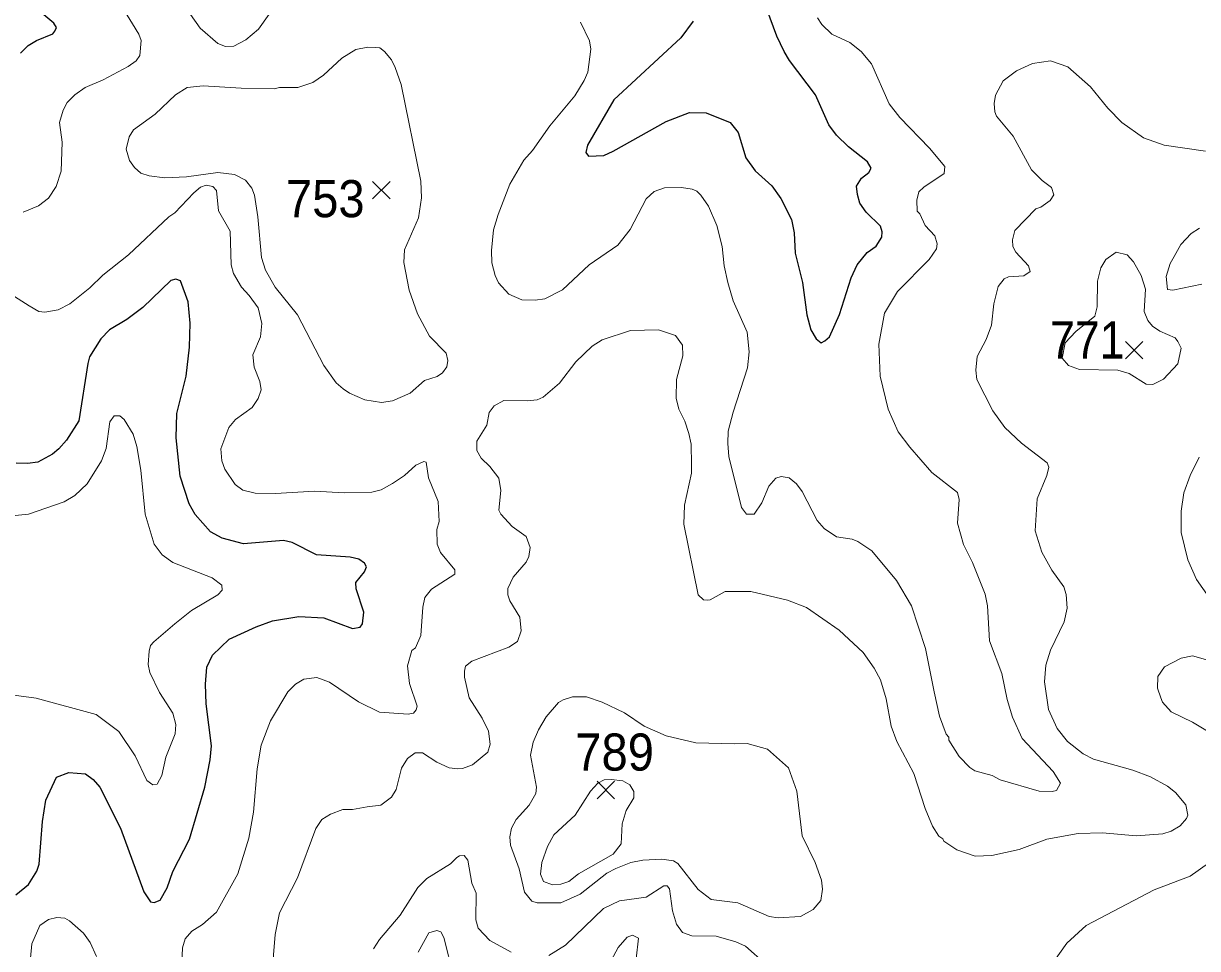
# Model space of a CAD drawing. Extents: x 294.2 to 320.3, y 7482.7 to 7510.7.
# Drawn here: x 305.089 to 307.621, y 7505.286 to 7507.28 of the extents above; entities that cross this region are included whole.
import ezdxf
from ezdxf.enums import TextEntityAlignment as Align

# ---------------------------------------------------------------- set-up
doc = ezdxf.new("R2010")
doc.units = 0
doc.header["$LTSCALE"] = 0.032
for name, color, linetype, lineweight in [('1', 7, 'Continuous', 25), ('2', 7, 'Continuous', 13), ('21', 7, 'Continuous', 25)]:
    doc.layers.add(name, color=color, linetype=linetype, lineweight=lineweight)
doc.layers.add('61', color=7, linetype='Continuous')

msp = doc.modelspace()

# ---------------------------------------------------------------- linework, layer by layer
at = {"layer": '1'}
for points in [[(305.0821, 7507.2166), (305.0986, 7507.2331), (305.1167, 7507.2441), (305.1517, 7507.2583), (305.1564, 7507.2638), (305.1596, 7507.2716), (305.154, 7507.2811), (305.1116, 7507.3164), (305.099, 7507.3337), (305.0861, 7507.3695)], [(306.5328, 7507.2852), (306.5061, 7507.2494), (306.3616, 7507.1158), (306.3048, 7507.0182), (306.3016, 7507.0025), (306.3071, 7506.9947), (306.3401, 7506.9962), (306.3606, 7507.0049), (306.4747, 7507.0695), (306.5254, 7507.0884), (306.5608, 7507.0876), (306.6127, 7507.0672), (306.63, 7507.0452), (306.6469, 7506.9909), (306.6666, 7506.9626), (306.7027, 7506.9304), (306.7224, 7506.9029), (306.7448, 7506.8581), (306.7511, 7506.829), (306.7527, 7506.785), (306.7687, 7506.722), (306.7782, 7506.652), (306.7868, 7506.6198), (306.7982, 7506.6009), (306.8092, 7506.5923), (306.8171, 7506.5962), (306.8273, 7506.6049), (306.8485, 7506.6528), (306.8737, 7506.7322), (306.887, 7506.7605), (306.9086, 7506.7864), (306.9275, 7506.8006), (306.9401, 7506.8195), (306.9409, 7506.8313), (306.9369, 7506.8438), (306.9058, 7506.874), (306.8922, 7506.8929), (306.8875, 7506.9117), (306.8851, 7506.9298), (306.8961, 7506.9471), (306.9118, 7506.9589), (306.9166, 7506.9684), (306.9087, 7506.9825), (306.8678, 7507.0147), (306.8419, 7507.0394), (306.8259, 7507.0622), (306.7966, 7507.1267), (306.7407, 7507.2006), (306.7295, 7507.2201), (306.7136, 7507.2533), (306.6921, 7507.3115)], [(305.072, 7505.4017), (305.0995, 7505.424), (305.1174, 7505.4528), (305.1225, 7505.4681), (305.1295, 7505.56), (305.1371, 7505.606), (305.1601, 7505.6558), (305.1863, 7505.666), (305.2221, 7505.6628), (305.2393, 7505.6507), (305.2534, 7505.6341), (305.298, 7505.5459), (305.3479, 7505.4081), (305.3625, 7505.387), (305.3702, 7505.3851), (305.3836, 7505.3902), (305.3989, 7505.417), (305.4111, 7505.4521), (305.4468, 7505.5217), (305.48, 7505.6341), (305.4915, 7505.6928), (305.4941, 7505.7235), (305.4826, 7505.8135), (305.4813, 7505.8563), (305.4839, 7505.8926), (305.4962, 7505.9185), (305.5324, 7505.9531), (305.5904, 7505.9799), (305.6258, 7505.9924), (305.6824, 7506.0019), (305.7362, 7505.9988), (305.7983, 7505.976), (305.8151, 7505.9787), (305.8201, 7505.9863), (305.8224, 7506.0115), (305.8064, 7506.0618), (305.8056, 7506.0752), (305.8245, 7506.098), (305.8282, 7506.109), (305.8243, 7506.1169), (305.8117, 7506.1255), (305.7936, 7506.1302), (305.7205, 7506.135), (305.6682, 7506.1617), (305.6493, 7506.1656), (305.5633, 7506.1585), (305.5169, 7506.1711), (305.4917, 7506.1845), (305.4587, 7506.2222), (305.4457, 7506.245), (305.4269, 7506.3048), (305.4178, 7506.3873), (305.4194, 7506.44), (305.4395, 7506.5201), (305.4466, 7506.583), (305.4481, 7506.6342), (305.4438, 7506.6806), (305.4273, 7506.7254), (305.417, 7506.7293), (305.4068, 7506.7262), (305.3463, 7506.668), (305.3114, 7506.6421), (305.2745, 7506.6201), (305.2556, 7506.6004), (305.2312, 7506.5619), (305.2273, 7506.5477), (305.208, 7506.4235), (305.1813, 7506.3819), (305.1652, 7506.3638), (305.151, 7506.352), (305.1196, 7506.3347), (305.0976, 7506.3316), (305.0732, 7506.3324)]]:
    msp.add_lwpolyline(points, dxfattribs=at)
at = {"layer": '2'}
for points in [[(305.088, 7506.874), (305.1212, 7506.8874), (305.1429, 7506.904), (305.1589, 7506.9289), (305.1697, 7506.9621), (305.1722, 7507.0247), (305.1665, 7507.0668), (305.1742, 7507.0936), (305.1831, 7507.1102), (305.1997, 7507.1268), (305.2214, 7507.1421), (305.2604, 7507.1587), (305.3146, 7507.1875), (305.3319, 7507.2003), (305.3395, 7507.2111), (305.3428, 7507.2437), (305.3377, 7507.2571), (305.2853, 7507.3439)], [(305.4034, 7507.3644), (305.4698, 7507.2705), (305.5081, 7507.2373), (305.5247, 7507.2309), (305.5426, 7507.2315), (305.5681, 7507.2449), (305.5956, 7507.2679), (305.6186, 7507.3005)], [(307.3163, 7505.6271), (307.3252, 7505.6424), (307.3093, 7505.6679), (307.2429, 7505.7388), (307.2218, 7505.7848), (307.2103, 7505.8231), (307.1988, 7505.8793), (307.172, 7505.9495), (307.1681, 7506.0248), (307.163, 7506.0504), (307.1356, 7506.1181), (307.1164, 7506.157), (307.103, 7506.2029), (307.1064, 7506.2539), (307.103, 7506.2695), (307.0481, 7506.3128), (307.0002, 7506.367), (306.9753, 7506.4002), (306.9536, 7506.4488), (306.9364, 7506.5203), (306.9332, 7506.5893), (306.9459, 7506.6556), (306.974, 7506.7029), (307.0417, 7506.7718), (307.0577, 7506.7948), (307.059, 7506.8051), (307.0545, 7506.8229), (307.0334, 7506.8452), (307.0219, 7506.8701), (307.0162, 7506.8759), (307.0156, 7506.8995), (307.0194, 7506.9174), (307.0302, 7506.9276), (307.0744, 7506.9568), (307.0756, 7506.9718), (307.0428, 7507.0114), (306.9786, 7507.0779), (306.9556, 7507.1074), (306.9177, 7507.1935), (306.8955, 7507.22), (306.8706, 7507.2392), (306.8323, 7507.2571), (306.8106, 7507.2781), (306.801, 7507.2929)], [(306.2903, 7507.2832), (306.3094, 7507.2431), (306.3126, 7507.2252), (306.3056, 7507.1754), (306.2979, 7507.1575), (306.2775, 7507.1243), (306.2238, 7507.0598), (306.1868, 7507.0068), (306.1677, 7506.9857), (306.1376, 7506.934), (306.1121, 7506.8689), (306.1025, 7506.8357), (306.098, 7506.791), (306.0987, 7506.7642), (306.1057, 7506.7374), (306.1134, 7506.7214), (306.1357, 7506.6971), (306.1632, 7506.685), (306.1926, 7506.6837), (306.213, 7506.6869), (306.2513, 7506.7061), (306.3088, 7506.7603), (306.3707, 7506.8025), (306.3975, 7506.8363), (306.432, 7506.9027), (306.4492, 7506.9181), (306.4709, 7506.9263), (306.508, 7506.927), (306.531, 7506.9232), (306.5412, 7506.9187), (306.5495, 7506.9104), (306.5661, 7506.8868), (306.584, 7506.8446), (306.5954, 7506.7999), (306.5999, 7506.7578), (306.6075, 7506.7221), (306.619, 7506.6825), (306.6497, 7506.6148), (306.6535, 7506.5726), (306.6504, 7506.5382), (306.619, 7506.4424), (306.6088, 7506.4015), (306.6075, 7506.3747), (306.6101, 7506.3473), (306.6376, 7506.2368), (306.6478, 7506.2227), (306.6644, 7506.2227), (306.681, 7506.247), (306.6963, 7506.2828), (306.711, 7506.3), (306.7225, 7506.3038), (306.7404, 7506.3013), (306.7557, 7506.2879), (306.7678, 7506.2713), (306.8004, 7506.2087), (306.8157, 7506.1914), (306.8425, 7506.1736), (306.8763, 7506.1685), (306.8885, 7506.1634), (306.9185, 7506.1436), (306.9715, 7506.0797), (307.0041, 7506.0248), (307.034, 7505.9329), (307.0526, 7505.8397), (307.0641, 7505.7873), (307.0785, 7505.7486), (307.0842, 7505.742), (307.0842, 7505.7353), (307.1068, 7505.7005), (307.1298, 7505.6762)], [(307.3399, 7506.0197), (307.3374, 7506.0491), (307.3323, 7506.0657), (307.3067, 7506.1021), (307.285, 7506.141), (307.271, 7506.187), (307.2748, 7506.256), (307.2958, 7506.3058), (307.3003, 7506.3236), (307.2965, 7506.3332), (307.2409, 7506.376), (307.2052, 7506.4098), (307.179, 7506.4456), (307.1451, 7506.5126), (307.1426, 7506.5331), (307.1458, 7506.5624), (307.165, 7506.5995), (307.1765, 7506.6301), (307.1816, 7506.6761), (307.1911, 7506.7137), (307.2039, 7506.7297), (307.2128, 7506.7342), (307.2461, 7506.7361), (307.2595, 7506.7456), (307.2562, 7506.7578), (307.2288, 7506.7872), (307.2224, 7506.7999), (307.2218, 7506.814), (307.2269, 7506.8344), (307.2719, 7506.8812), (307.2828, 7506.8845), (307.3029, 7506.899), (307.311, 7506.9113), (307.3058, 7506.9269), (307.2856, 7506.9417), (307.2626, 7506.9647), (307.223, 7507.0375), (307.1873, 7507.0809), (307.1834, 7507.0898), (307.1822, 7507.1077), (307.1854, 7507.1256), (307.2013, 7507.1568), (307.2307, 7507.1786), (307.2652, 7507.1945), (307.3035, 7507.2003), (307.3412, 7507.1868), (307.3903, 7507.144), (307.4274, 7507.0981), (307.4574, 7507.0668), (307.504, 7507.0336), (307.5487, 7507.0183), (307.6381, 7507.0049)], [(305.5451, 7506.2866), (305.5228, 7506.3198), (305.5164, 7506.3377), (305.5145, 7506.3632), (305.5317, 7506.4092), (305.5458, 7506.4264), (305.5822, 7506.4526), (305.5949, 7506.4718), (305.6013, 7506.4909), (305.5981, 7506.5088), (305.586, 7506.5394), (305.5834, 7506.5663), (305.6, 7506.6046), (305.6026, 7506.6339), (305.5949, 7506.6671), (305.5752, 7506.694), (305.5592, 7506.7118), (305.5413, 7506.7412), (305.5368, 7506.7604), (305.5343, 7506.8325), (305.5094, 7506.8766), (305.5049, 7506.9206), (305.4972, 7506.9289), (305.4825, 7506.9321), (305.4703, 7506.9275), (305.4561, 7506.9152), (305.4148, 7506.8723), (305.4021, 7506.8638), (305.3153, 7506.782), (305.2597, 7506.738), (305.2317, 7506.7105), (305.1889, 7506.676), (305.1634, 7506.6633), (305.1346, 7506.6582), (305.1218, 7506.6595), (305.1008, 7506.6716), (305.0267, 7506.7182)], [(307.6253, 7506.8395), (307.6074, 7506.8274), (307.5851, 7506.8038), (307.5704, 7506.7782), (307.5621, 7506.7629), (307.5532, 7506.7348), (307.5557, 7506.7073), (307.5679, 7506.7054), (307.6304, 7506.7182)], [(306.0502, 7505.8269), (306.04, 7505.8709), (306.04, 7505.8843), (306.0419, 7505.8946), (306.0553, 7505.9054), (306.1353, 7505.9359), (306.1543, 7505.9482), (306.1623, 7505.9713), (306.1594, 7506.0008), (306.1376, 7506.0359), (306.133, 7506.0484), (306.1336, 7506.0623), (306.1445, 7506.0868), (306.1732, 7506.1191), (306.1784, 7506.1313), (306.1818, 7506.1506), (306.1727, 7506.1745), (306.1428, 7506.1957), (306.1181, 7506.2224), (306.1141, 7506.2313), (306.1181, 7506.2739), (306.1141, 7506.3001), (306.0946, 7506.3257), (306.0756, 7506.3432), (306.0665, 7506.3599), (306.0665, 7506.38), (306.0883, 7506.4145), (306.0929, 7506.4417), (306.1038, 7506.4564), (306.1249, 7506.4679), (306.176, 7506.4666), (306.1964, 7506.4692), (306.2092, 7506.475), (306.2449, 7506.505), (306.2799, 7506.5512), (306.3151, 7506.5848), (306.3369, 7506.5988), (306.3982, 7506.6186), (306.4582, 7506.6199), (306.4946, 7506.6078), (306.5099, 7506.5873), (306.5105, 7506.5637), (306.4971, 7506.5126), (306.4964, 7506.473), (306.5022, 7506.4488), (306.515, 7506.4232), (306.5239, 7506.3964), (306.5284, 7506.3734), (306.5296, 7506.3288), (306.5296, 7506.3109), (306.5143, 7506.2419), (306.5131, 7506.2011), (306.5437, 7506.0484), (306.5552, 7506.0382), (306.5629, 7506.037), (306.5699, 7506.0376), (306.6018, 7506.0561), (306.6574, 7506.0561), (306.7366, 7506.037), (306.7774, 7506.0216), (306.8476, 7505.9724), (306.9, 7505.9246), (306.9236, 7505.8908), (306.937, 7505.8652), (306.9492, 7505.8244), (306.96, 7505.7656), (306.9722, 7505.7324), (307.0092, 7505.6635), (307.0334, 7505.5881), (307.0494, 7505.5498), (307.0628, 7505.5287), (307.0718, 7505.523), (307.0736, 7505.5178), (307.1017, 7505.4987), (307.1414, 7505.4853), (307.1771, 7505.4866), (307.2358, 7505.4994), (307.2959, 7505.5223), (307.3635, 7505.5344), (307.4159, 7505.5357), (307.4887, 7505.5293), (307.5461, 7505.5338), (307.564, 7505.5389), (307.5831, 7505.5504), (307.5972, 7505.5664), (307.5997, 7505.5734), (307.5959, 7505.5958), (307.5736, 7505.6226), (307.5564, 7505.636), (307.5193, 7505.6564), (307.481, 7505.6705), (307.3967, 7505.6947), (307.3744, 7505.7062), (307.3405, 7505.7324), (307.3182, 7505.7605)], [(305.0063, 7506.2132), (305.0995, 7506.2227), (305.1761, 7506.2495), (305.1991, 7506.263), (305.2259, 7506.2878), (305.2572, 7506.3377), (305.2667, 7506.3645), (305.2751, 7506.4219), (305.284, 7506.4347), (305.2968, 7506.4347), (305.3057, 7506.427), (305.3249, 7506.3952), (305.3331, 7506.3683), (305.3421, 7506.3173), (305.351, 7506.2228), (305.3702, 7506.1576), (305.3875, 7506.1346), (305.4111, 7506.1187), (305.4953, 7506.0855), (305.5164, 7506.0695), (305.517, 7506.0586), (305.5075, 7506.0484), (305.4513, 7506.0152), (305.4149, 7505.9859), (305.3695, 7505.9471), (305.3626, 7505.9393), (305.3598, 7505.927), (305.3575, 7505.8986), (305.3615, 7505.8814), (305.3823, 7505.8384), (305.411, 7505.7937), (305.4174, 7505.7694), (305.4155, 7505.749), (305.396, 7505.6986), (305.3868, 7505.659), (305.377, 7505.6409), (305.3673, 7505.6392), (305.3546, 7505.6481), (305.3294, 7505.7016), (305.2944, 7505.7541), (305.2456, 7505.7909), (305.1161, 7505.8263), (305.0574, 7505.8339)], [(305.4297, 7505.2384), (305.4314, 7505.2874), (305.4371, 7505.3072), (305.4515, 7505.3233), (305.475, 7505.3378), (305.5049, 7505.3645), (305.5509, 7505.447), (305.5745, 7505.5243), (305.5847, 7505.5805), (305.5924, 7505.6737), (305.6013, 7505.7248), (305.6211, 7505.7771), (305.6588, 7505.8397), (305.6754, 7505.8563), (305.6933, 7505.8671), (305.7214, 7505.8703), (305.7488, 7505.8607), (305.8114, 7505.818), (305.8567, 7505.7956), (305.918, 7505.7918), (305.9301, 7505.7937), (305.9359, 7505.8007), (305.9378, 7505.809), (305.9212, 7505.8576), (305.9167, 7505.8959), (305.9263, 7505.9284), (305.934, 7505.9348), (305.9455, 7505.961), (305.9499, 7506.0223), (305.9544, 7506.0427), (305.9684, 7506.0612), (306.0189, 7506.0931), (306.0189, 7506.1027), (305.9882, 7506.1398), (305.9806, 7506.1576), (305.98, 7506.1896), (305.9851, 7506.2068), (305.9831, 7506.2502), (305.9621, 7506.3007), (305.957, 7506.3345), (305.9518, 7506.3364), (305.9346, 7506.3281), (305.9103, 7506.3057), (305.8848, 7506.2885), (305.8599, 7506.2751), (305.8401, 7506.27)], [(307.624, 7506.3454), (307.6048, 7506.3058), (307.5915, 7506.2687), (307.5857, 7506.2291), (307.5857, 7506.1832), (307.5997, 7506.1244), (307.6183, 7506.0816), (307.6457, 7506.0427)], [(305.8401, 7506.27), (305.7801, 7506.2687), (305.7163, 7506.2725), (305.632, 7506.2674), (305.5886, 7506.2681), (305.5618, 7506.2745), (305.5451, 7506.2866)], [(307.3182, 7505.7605), (307.2997, 7505.8014), (307.2907, 7505.8614), (307.2939, 7505.8971), (307.3035, 7505.9291), (307.3329, 7505.9904), (307.3399, 7506.0197)], [(307.6496, 7505.7503), (307.61, 7505.7739), (307.564, 7505.7962), (307.5455, 7505.8173), (307.5417, 7505.8269), (307.5346, 7505.8473), (307.5353, 7505.8729), (307.5493, 7505.8933), (307.5857, 7505.9124), (307.61, 7505.9169), (307.7211, 7505.8856)], [(306.0358, 7505.6741), (306.057, 7505.6825), (306.0903, 7505.7095), (306.0955, 7505.7267), (306.0915, 7505.7546), (306.0783, 7505.783), (306.0502, 7505.8269)], [(305.6244, 7505.2285), (305.6313, 7505.3167), (305.641, 7505.3635), (305.6799, 7505.4387), (305.7194, 7505.5453), (305.7322, 7505.5645), (305.7508, 7505.576), (305.7774, 7505.5862), (305.7986, 7505.5856), (305.8296, 7505.5918), (305.8595, 7505.5951), (305.8825, 7505.6127), (305.8928, 7505.6294), (305.9037, 7505.675), (305.9169, 7505.6962), (305.9336, 7505.7084), (305.9491, 7505.7084), (305.9801, 7505.6881), (306.0065, 7505.6758), (306.0254, 7505.6736), (306.0358, 7505.6741)], [(307.1298, 7505.6762), (307.1407, 7505.6692), (307.1777, 7505.659), (307.195, 7505.65), (307.2793, 7505.6258), (307.3074, 7505.6245), (307.3163, 7505.6271)], [(306.1402, 7505.2784), (306.0943, 7505.3033), (306.0693, 7505.3302), (306.0642, 7505.3481), (306.0648, 7505.4055), (306.0553, 7505.4272), (306.0472, 7505.477), (306.0392, 7505.487), (306.0289, 7505.4862), (306.0232, 7505.4823), (306.0094, 7505.4689), (305.9587, 7505.437), (305.9393, 7505.4177), (305.9008, 7505.3583), (305.8567, 7505.3059), (305.8433, 7505.2855)], [(307.3035, 7505.2484), (307.3386, 7505.2976), (307.3808, 7505.3359), (307.5276, 7505.4131), (307.6049, 7505.4425), (307.6445, 7505.47)], [(306.6897, 7505.2522), (306.6461, 7505.2914), (306.6254, 7505.3009), (306.5823, 7505.3126), (306.5301, 7505.3139), (306.51, 7505.3211), (306.4968, 7505.3384), (306.4888, 7505.3674), (306.4819, 7505.4152), (306.4773, 7505.4214), (306.4698, 7505.4214), (306.4314, 7505.3972), (306.3739, 7505.3889), (306.3394, 7505.3723), (306.2577, 7505.2938), (306.2219, 7505.2714)], [(305.1, 7505.2267), (305.1069, 7505.2966), (305.1241, 7505.3361), (305.1425, 7505.3489), (305.1603, 7505.3534), (305.1781, 7505.3517), (305.1879, 7505.3456), (305.2183, 7505.3194), (305.2327, 7505.2991), (305.2459, 7505.269)], [(306.0161, 7505.2282), (305.9954, 7505.3103), (305.9885, 7505.322), (305.9805, 7505.3248), (305.9627, 7505.3203), (305.9397, 7505.2786)], [(306.4098, 7505.2642), (306.4149, 7505.3088), (306.4023, 7505.3152), (306.3908, 7505.3107), (306.3713, 7505.2885), (306.3311, 7505.214)]]:
    msp.add_lwpolyline(points, dxfattribs=at)
for points in [[(305.6409, 7507.1424), (305.6294, 7507.1396), (305.5579, 7507.1408), (305.4762, 7507.146), (305.4417, 7507.1421), (305.4162, 7507.1268), (305.3728, 7507.0847), (305.3261, 7507.0509), (305.3165, 7507.0362), (305.3102, 7507.0094), (305.3172, 7506.9851), (305.3281, 7506.9698), (305.3421, 7506.9576), (305.36, 7506.9519), (305.3932, 7506.948), (305.44, 7506.9498), (305.5081, 7506.9595), (305.5439, 7506.9551), (305.5673, 7506.9428), (305.5811, 7506.9256), (305.5871, 7506.91), (305.5943, 7506.8638), (305.602, 7506.7757), (305.6109, 7506.7489), (305.6313, 7506.7118), (305.6799, 7506.6524), (305.7361, 7506.5433), (305.7631, 7506.5058), (305.7782, 7506.4928), (305.7916, 7506.4832), (305.8248, 7506.4692), (305.8606, 7506.4635), (305.8848, 7506.4673), (305.9229, 7506.4834), (305.9534, 7506.5109), (305.9806, 7506.5195), (305.9922, 7506.527), (306.0016, 7506.5399), (306.0038, 7506.5539), (306.0004, 7506.5694), (305.964, 7506.6065), (305.9384, 7506.6544), (305.9205, 7506.7055), (305.909, 7506.7655), (305.9103, 7506.7923), (305.9404, 7506.8612), (305.9474, 7506.9047), (305.9455, 7506.9404), (305.9033, 7507.1486), (305.8905, 7507.1856), (305.8822, 7507.2022), (305.8676, 7507.22), (305.8574, 7507.2277), (305.8478, 7507.229), (305.8312, 7507.2296), (305.8057, 7507.2245), (305.775, 7507.2054), (305.7354, 7507.1689), (305.713, 7507.153), (305.6805, 7507.1428)], [(307.5786, 7506.5949), (307.5723, 7506.6026), (307.5398, 7506.6173), (307.5238, 7506.6282), (307.5136, 7506.6403), (307.5059, 7506.6595), (307.5085, 7506.708), (307.4995, 7506.7374), (307.4829, 7506.7667), (307.4689, 7506.782), (307.4452, 7506.7878), (307.4229, 7506.7718), (307.412, 7506.754), (307.405, 7506.7246), (307.4044, 7506.6697), (307.3991, 7506.6497), (307.3585, 7506.6163), (307.3351, 7506.5922), (307.329, 7506.5592), (307.3425, 7506.5433), (307.3661, 7506.5343), (307.4491, 7506.533), (307.4734, 7506.526), (307.5097, 7506.503), (307.5244, 7506.5024), (307.5474, 7506.5139), (307.578, 7506.5464), (307.5857, 7506.5803)], [(306.2526, 7505.8224), (306.2424, 7505.8167), (306.2162, 7505.7854), (306.1996, 7505.758), (306.1881, 7505.7311), (306.1823, 7505.703), (306.1951, 7505.6341), (306.1938, 7505.6206), (306.1792, 7505.5951), (306.1511, 7505.5645), (306.1415, 7505.546), (306.1376, 7505.5268), (306.1389, 7505.5089), (306.1574, 7505.4579), (306.1689, 7505.408), (306.1849, 7505.3883), (306.1964, 7505.3844), (306.2475, 7505.385), (306.2896, 7505.4036), (306.3469, 7505.4487), (306.3663, 7505.4589), (306.3987, 7505.4719), (306.4242, 7505.4768), (306.4658, 7505.4789), (306.4907, 7505.4751), (306.4996, 7505.4693), (306.5437, 7505.4132), (306.5718, 7505.3921), (306.6293, 7505.3844), (306.697, 7505.3551), (306.7161, 7505.3525), (306.7647, 7505.3551), (306.7921, 7505.3704), (306.8087, 7505.3901), (306.8119, 7505.4145), (306.81, 7505.4336), (306.7959, 7505.4719), (306.7678, 7505.5294), (306.7569, 7505.6252), (306.7385, 7505.6756), (306.6937, 7505.7158), (306.6497, 7505.7279), (306.6229, 7505.7273), (306.5386, 7505.7298), (306.4747, 7505.7444), (306.4275, 7505.7654), (306.3848, 7505.7943), (306.3369, 7505.8173), (306.303, 7505.8288), (306.273, 7505.8288)], [(306.3885, 7505.5836), (306.3802, 7505.5549), (306.3777, 7505.5121), (306.3605, 7505.4898), (306.2858, 7505.447), (306.2647, 7505.431), (306.2475, 7505.4246), (306.2296, 7505.4233), (306.2104, 7505.431), (306.204, 7505.4464), (306.2066, 7505.4719), (306.2187, 7505.5064), (306.2322, 7505.5313), (306.2788, 7505.574), (306.3113, 7505.6251), (306.3271, 7505.6427), (306.3409, 7505.6497), (306.3565, 7505.6508), (306.3814, 7505.6475), (306.3962, 7505.6392), (306.4052, 7505.6245), (306.4052, 7505.6111)]]:
    msp.add_lwpolyline(points, close=True, dxfattribs=at)
at = {"layer": '21'}
for p, q in [((305.8417, 7506.9399), (305.8792, 7506.9024)), ((305.8792, 7506.9399), (305.8417, 7506.9024)), ((307.4657, 7506.5947), (307.5032, 7506.5572)), ((307.5032, 7506.5947), (307.4657, 7506.5572)), ((306.3259, 7505.6467), (306.3634, 7505.6092)), ((306.3634, 7505.6467), (306.3259, 7505.6092))]:
    msp.add_line(p, q, dxfattribs=at)

# ---------------------------------------------------------------- texts
at = {"layer": '61'}
for s, width, p in [('753', 0.95, (305.7396, 7506.8628)), ('771', 0.9, (307.3831, 7506.5582)), ('789', 0.95, (306.3636, 7505.6698))]:
    msp.add_text(s, height=0.08, dxfattribs=dict(at, width=width)).set_placement(p, align=Align.CENTER)

doc.saveas('drawing.dxf')
